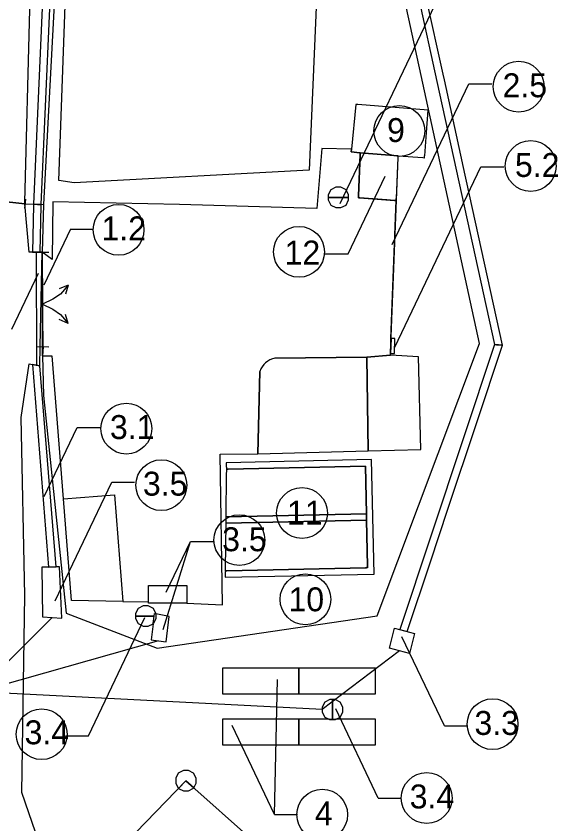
# Model space of a CAD drawing. Extents: x -438410 to -437811, y -1133174 to -1132817.
# Drawn here: x -438365.3 to -438322.9, y -1133117.4 to -1133054 of the extents above; entities that cross this region are included whole.
import ezdxf

# ---------------------------------------------------------------- set-up
doc = ezdxf.new("R2010")
doc.units = 0
for name, color, linetype in [('11 - bourané objekty', 7, 'Continuous'), ('12 - žlaby', 7, 'Continuous'), ('13 - propustky', 7, 'Continuous'), ('16 - betonové plochy', 7, 'Continuous'), ('17 - panel', 7, 'Continuous'), ('18 - asfalt', 7, 'Continuous'), ('20 - popisy', 7, 'Continuous'), ('3 - ploty a brány', 7, 'Continuous'), ('5 - obrubníky', 7, 'Continuous'), ('6 - kanalizace + šachty', 7, 'Continuous'), ('7 - elektro', 7, 'Continuous')]:
    doc.layers.add(name, color=color, linetype=linetype)

msp = doc.modelspace()

# ---------------------------------------------------------------- linework, layer by layer
at = {"layer": '11 - bourané objekty'}
for p, q in [((-438338.695, -1133060.976), (-438339.034, -1133064.474)), ((-438339.035, -1133064.486), (-438339.055, -1133064.69)), ((-438339.055, -1133064.69), (-438338.376, -1133064.756)), ((-438333.308, -1133065.146), (-438333.304, -1133065.096)), ((-438333.304, -1133065.096), (-438333.304, -1133064.996)), ((-438337.459, -1133088.816), (-438348.852, -1133089.066)), ((-438337.27, -1133097.786), (-438337.459, -1133088.816)), ((-438348.852, -1133089.066), (-438348.845, -1133089.416)), ((-438348.844, -1133089.416), (-438348.844, -1133089.465)), ((-438348.844, -1133089.465), (-438348.842, -1133089.565)), ((-438337.869, -1133093.065), (-438337.948, -1133089.331)), ((-438337.869, -1133093.065), (-438348.89, -1133093.299)), ((-438348.89, -1133093.299), (-438337.869, -1133093.065)), ((-438337.858, -1133093.565), (-438337.869, -1133093.065)), ((-438337.858, -1133093.565), (-438348.888, -1133093.8)), ((-438348.888, -1133093.8), (-438337.858, -1133093.565)), ((-438337.783, -1133097.146), (-438337.858, -1133093.565)), ((-438348.874, -1133097.576), (-438348.943, -1133097.576)), ((-438348.874, -1133097.533), (-438348.874, -1133097.576)), ((-438337.934, -1133097.296), (-438337.854, -1133097.296)), ((-438337.854, -1133097.296), (-438337.854, -1133097.256)), ((-438337.854, -1133097.256), (-438337.784, -1133097.256)), ((-438337.784, -1133097.256), (-438337.784, -1133097.146)), ((-438348.934, -1133098.035), (-438337.27, -1133097.786))]:
    msp.add_line(p, q, dxfattribs=at)
msp.add_lwpolyline([(-438360.783, -1133067.104), (-438361.974, -1133066.926), (-438360.619, -1133029.346), (-438340.823, -1133030.216), (-438342.346, -1133066.119)], close=True, dxfattribs=at)
for points in [[(-438338.642, -1133060.976), (-438338.694, -1133060.976), (-438338.695, -1133060.976)], [(-438333.019, -1133061.41), (-438338.545, -1133060.983), (-438338.642, -1133060.976)], [(-438333.297, -1133064.996), (-438333.156, -1133063.178), (-438333.019, -1133061.41)], [(-438339.034, -1133064.486), (-438339.035, -1133064.486), (-438339.035, -1133064.486)], [(-438339.034, -1133064.474), (-438339.034, -1133064.485), (-438339.034, -1133064.486)], [(-438338.376, -1133064.756), (-438338.345, -1133064.756), (-438338.344, -1133064.756)], [(-438338.344, -1133064.756), (-438338.344, -1133064.759), (-438338.344, -1133064.759)], [(-438338.344, -1133064.759), (-438335.364, -1133064.989), (-438333.454, -1133065.136), (-438333.334, -1133065.146)], [(-438333.334, -1133065.146), (-438333.308, -1133065.146), (-438333.308, -1133065.146)], [(-438333.304, -1133064.996), (-438333.297, -1133064.996)], [(-438348.845, -1133089.416), (-438348.844, -1133089.416)], [(-438348.842, -1133089.565), (-438348.694, -1133089.561), (-438337.948, -1133089.331)], [(-438337.948, -1133089.331), (-438348.694, -1133089.561), (-438348.842, -1133089.565)], [(-438337.948, -1133089.331), (-438337.869, -1133093.065), (-438337.858, -1133093.565), (-438337.783, -1133097.146), (-438337.78, -1133097.256), (-438337.78, -1133097.256), (-438337.779, -1133097.299)], [(-438348.842, -1133089.565), (-438348.844, -1133089.716), (-438348.847, -1133089.906), (-438348.89, -1133093.299)], [(-438348.89, -1133093.299), (-438348.89, -1133093.3), (-438348.896, -1133093.799)], [(-438348.896, -1133093.799), (-438348.942, -1133097.386), (-438348.944, -1133097.535)], [(-438348.888, -1133093.8), (-438348.896, -1133093.799)], [(-438348.896, -1133093.799), (-438348.888, -1133093.8)], [(-438348.944, -1133097.535), (-438348.874, -1133097.533), (-438348.794, -1133097.531), (-438337.934, -1133097.302)], [(-438348.943, -1133097.576), (-438348.941, -1133097.686), (-438348.934, -1133098.035)], [(-438337.934, -1133097.302), (-438348.794, -1133097.531), (-438348.874, -1133097.533)], [(-438337.934, -1133097.302), (-438337.934, -1133097.296)], [(-438337.779, -1133097.299), (-438337.784, -1133097.299), (-438337.854, -1133097.3), (-438337.854, -1133097.3), (-438337.934, -1133097.302)], [(-438337.784, -1133097.146), (-438337.783, -1133097.146)], [(-438337.779, -1133097.299), (-438337.779, -1133097.299)]]:
    msp.add_lwpolyline(points, dxfattribs=at)
at = {"layer": '12 - žlaby'}
for p, q in [((-438334.391, -1133049.825), (-438332.344, -1133059.164)), ((-438331.85, -1133058.606), (-438333.72, -1133050.084)), ((-438363.354, -1133068.817), (-438362.677, -1133053.437)), ((-438331.756, -1133059.035), (-438331.85, -1133058.606)), ((-438331.85, -1133058.606), (-438331.85, -1133058.606)), ((-438330.118, -1133066.503), (-438331.756, -1133059.035)), ((-438332.344, -1133059.164), (-438327.822, -1133079.8)), ((-438330.01, -1133066.994), (-438330.118, -1133066.503)), ((-438330.118, -1133066.503), (-438330.118, -1133066.503)), ((-438327.193, -1133079.837), (-438330.01, -1133066.994)), ((-438363.954, -1133068.796), (-438363.954, -1133068.796)), ((-438363.438, -1133072.554), (-438363.356, -1133068.882)), ((-438363.357, -1133068.882), (-438363.354, -1133068.817)), ((-438363.438, -1133072.554), (-438363.438, -1133072.554)), ((-438327.822, -1133079.8), (-438335.254, -1133102.137)), ((-438329.241, -1133085.984), (-438327.193, -1133079.837)), ((-438327.822, -1133079.8), (-438327.193, -1133079.837)), ((-438327.664, -1133079.809), (-438327.822, -1133079.8)), ((-438327.55, -1133079.816), (-438327.514, -1133079.816)), ((-438327.514, -1133079.816), (-438327.514, -1133079.818)), ((-438327.514, -1133079.818), (-438327.193, -1133079.837)), ((-438363.457, -1133081.454), (-438364.035, -1133081.349)), ((-438364.035, -1133081.349), (-438362.776, -1133097.231)), ((-438362.175, -1133097.219), (-438363.457, -1133081.454))]:
    msp.add_line(p, q, dxfattribs=at)
for points in [[(-438360.442, -1133026.495), (-438362.04, -1133027.991), (-438363.276, -1133053.408), (-438363.954, -1133068.796)], [(-438331.85, -1133058.606), (-438331.85, -1133058.606)], [(-438330.118, -1133066.503), (-438330.118, -1133066.503)], [(-438363.954, -1133068.796), (-438363.955, -1133068.856), (-438364.038, -1133072.559)], [(-438363.954, -1133068.796), (-438363.654, -1133068.806), (-438363.354, -1133068.817)], [(-438363.354, -1133068.817), (-438363.654, -1133068.806), (-438363.954, -1133068.796)], [(-438363.356, -1133068.882), (-438363.357, -1133068.882)], [(-438364.038, -1133072.559), (-438363.762, -1133072.557), (-438363.737, -1133072.557), (-438363.737, -1133072.557), (-438363.438, -1133072.554)], [(-438327.822, -1133079.8), (-438327.664, -1133079.809), (-438327.55, -1133079.816)], [(-438327.193, -1133079.837), (-438327.514, -1133079.818), (-438327.514, -1133079.818), (-438327.55, -1133079.816), (-438327.664, -1133079.809)], [(-438334.674, -1133102.291), (-438332.849, -1133096.813), (-438331.48, -1133092.702), (-438329.241, -1133085.984)], [(-438362.776, -1133097.231), (-438362.776, -1133097.231), (-438362.175, -1133097.219)], [(-438335.254, -1133102.137), (-438335.254, -1133102.137)], [(-438335.254, -1133102.137), (-438334.674, -1133102.291), (-438334.674, -1133102.291)]]:
    msp.add_lwpolyline(points, dxfattribs=at)
at = {"layer": '13 - propustky'}
msp.add_line((-438363.737, -1133072.502), (-438363.728, -1133081.376), dxfattribs=at)
at = {"layer": '16 - betonové plochy'}
for p, q in [((-438335.364, -1133064.989), (-438338.344, -1133064.756)), ((-438338.344, -1133064.756), (-438338.344, -1133064.906)), ((-438338.351, -1133064.905), (-438338.486, -1133068.136)), ((-438335.519, -1133068.346), (-438335.368, -1133065.118)), ((-438335.368, -1133065.116), (-438335.364, -1133065.116)), ((-438335.364, -1133065.116), (-438335.364, -1133064.989)), ((-438338.486, -1133068.136), (-438338.492, -1133068.286)), ((-438338.492, -1133068.286), (-438338.394, -1133068.286)), ((-438335.526, -1133068.496), (-438335.524, -1133068.455)), ((-438335.524, -1133068.455), (-438335.524, -1133068.346)), ((-438335.988, -1133080.621), (-438337.82, -1133080.768)), ((-438333.795, -1133080.755), (-438335.988, -1133080.621)), ((-438337.82, -1133080.768), (-438345.037, -1133080.865)), ((-438337.72, -1133088.126), (-438337.82, -1133080.768)), ((-438337.82, -1133080.768), (-438337.72, -1133088.126)), ((-438333.593, -1133088.01), (-438333.795, -1133080.755)), ((-438346.226, -1133081.897), (-438346.377, -1133088.367)), ((-438346.377, -1133088.367), (-438337.72, -1133088.126)), ((-438337.72, -1133088.126), (-438333.593, -1133088.01))]:
    msp.add_line(p, q, dxfattribs=at)
for points in [[(-438338.344, -1133064.906), (-438338.351, -1133064.905)], [(-438335.368, -1133065.118), (-438335.368, -1133065.116)], [(-438338.394, -1133068.286), (-438338.395, -1133068.293)], [(-438338.395, -1133068.293), (-438335.674, -1133068.487), (-438335.554, -1133068.496)], [(-438335.554, -1133068.496), (-438335.526, -1133068.496), (-438335.526, -1133068.496)], [(-438335.524, -1133068.346), (-438335.519, -1133068.346)]]:
    msp.add_lwpolyline(points, dxfattribs=at)
msp.add_lwpolyline([(-438361.602, -1133091.889), (-438357.615, -1133091.57), (-438356.947, -1133099.927), (-438360.987, -1133099.86)], close=True, dxfattribs=at)
msp.add_arc((-438344.71, -1133082.442), 1.611, 101.67972, 160.23687, dxfattribs=at)
at = {"layer": '17 - panel'}
for p, q in [((-438367.085, -1133068.499), (-438364.634, -1133068.771)), ((-438364.633, -1133068.772), (-438367.085, -1133068.499)), ((-438364.634, -1133068.771), (-438364.634, -1133068.626)), ((-438364.285, -1133072.562), (-438364.633, -1133068.772)), ((-438364.038, -1133072.559), (-438364.285, -1133072.562)), ((-438363.762, -1133072.557), (-438364.038, -1133072.559)), ((-438364.038, -1133072.559), (-438364.038, -1133072.56)), ((-438364.923, -1133085.522), (-438364.289, -1133081.304)), ((-438364.631, -1133099.471), (-438364.923, -1133085.522)), ((-438364.863, -1133114.9), (-438364.631, -1133099.471)), ((-438349.157, -1133105.17), (-438349.157, -1133107.17)), ((-438343.157, -1133105.17), (-438349.157, -1133105.17)), ((-438343.157, -1133107.17), (-438343.157, -1133105.17)), ((-438337.157, -1133105.17), (-438343.157, -1133105.17)), ((-438343.157, -1133105.17), (-438343.157, -1133107.17)), ((-438337.157, -1133107.17), (-438337.157, -1133105.17)), ((-438349.157, -1133107.17), (-438343.157, -1133107.17)), ((-438343.157, -1133107.17), (-438337.157, -1133107.17)), ((-438349.157, -1133109.17), (-438349.157, -1133111.17)), ((-438343.157, -1133109.17), (-438349.157, -1133109.17)), ((-438343.157, -1133111.17), (-438343.157, -1133109.17)), ((-438343.157, -1133109.17), (-438343.157, -1133111.17)), ((-438340.812, -1133109.17), (-438343.157, -1133109.17)), ((-438340.725, -1133109.214), (-438340.812, -1133109.17)), ((-438340.239, -1133109.17), (-438340.325, -1133109.214)), ((-438337.157, -1133109.17), (-438340.239, -1133109.17)), ((-438337.157, -1133111.17), (-438337.157, -1133109.17)), ((-438349.157, -1133111.17), (-438343.157, -1133111.17)), ((-438343.157, -1133111.17), (-438337.157, -1133111.17)), ((-438361.996, -1133123.207), (-438364.863, -1133114.9))]:
    msp.add_line(p, q, dxfattribs=at)
for points in [[(-438364.63, -1133068.626), (-438364.248, -1133053.526), (-438364.244, -1133053.376), (-438364.244, -1133053.371)], [(-438364.634, -1133068.626), (-438364.63, -1133068.626)], [(-438364.038, -1133072.56), (-438364.038, -1133072.559)], [(-438363.282, -1133072.553), (-438363.438, -1133072.554), (-438363.737, -1133072.557), (-438363.762, -1133072.557)], [(-438363.762, -1133072.557), (-438363.762, -1133072.557)], [(-438363.457, -1133081.454), (-438363.428, -1133079.95), (-438363.282, -1133072.553)], [(-438364.289, -1133081.304), (-438364.035, -1133081.349), (-438363.457, -1133081.454)], [(-438340.325, -1133109.214), (-438340.525, -1133109.214), (-438340.725, -1133109.214)]]:
    msp.add_lwpolyline(points, dxfattribs=at)
at = {"layer": '18 - asfalt'}
for p, q in [((-438341.362, -1133064.433), (-438341.744, -1133069.128)), ((-438339.034, -1133064.485), (-438341.362, -1133064.433)), ((-438339.055, -1133064.69), (-438339.034, -1133064.485)), ((-438338.376, -1133064.756), (-438339.055, -1133064.69)), ((-438362.435, -1133068.596), (-438362.482, -1133073.127)), ((-438352.505, -1133068.804), (-438362.435, -1133068.596)), ((-438335.939, -1133079.319), (-438335.526, -1133068.496)), ((-438335.526, -1133068.496), (-438335.554, -1133068.496)), ((-438341.744, -1133069.128), (-438352.505, -1133068.804)), ((-438363.243, -1133080.683), (-438363.282, -1133072.553)), ((-438362.482, -1133073.127), (-438363.282, -1133072.553)), ((-438363.282, -1133072.553), (-438363.263, -1133076.618)), ((-438363.263, -1133076.618), (-438363.243, -1133080.683)), ((-438335.954, -1133079.717), (-438335.943, -1133079.319)), ((-438335.943, -1133079.319), (-438335.939, -1133079.319)), ((-438337.82, -1133080.768), (-438335.988, -1133080.621)), ((-438363.243, -1133080.683), (-438362.521, -1133080.664)), ((-438362.521, -1133080.664), (-438361.624, -1133091.891)), ((-438345.037, -1133080.864), (-438337.82, -1133080.768)), ((-438346.377, -1133088.367), (-438346.226, -1133081.897)), ((-438349.335, -1133088.397), (-438346.377, -1133088.367)), ((-438349.15, -1133100.206), (-438349.335, -1133088.397)), ((-438361.624, -1133091.891), (-438361.602, -1133091.889)), ((-438361.602, -1133091.889), (-438357.615, -1133091.57)), ((-438357.615, -1133091.57), (-438356.947, -1133099.927)), ((-438354.945, -1133099.96), (-438354.945, -1133098.677)), ((-438354.945, -1133098.677), (-438351.945, -1133098.677)), ((-438351.945, -1133098.677), (-438351.945, -1133100.063)), ((-438356.947, -1133099.927), (-438354.945, -1133099.96)), ((-438351.945, -1133100.063), (-438349.15, -1133100.206))]:
    msp.add_line(p, q, dxfattribs=at)
for points in [[(-438338.492, -1133068.286), (-438338.486, -1133068.136), (-438338.351, -1133064.905), (-438338.345, -1133064.758)], [(-438338.345, -1133064.758), (-438338.345, -1133064.758), (-438338.376, -1133064.756)], [(-438338.376, -1133064.756), (-438338.376, -1133064.756)], [(-438336.259, -1133068.444), (-438338.395, -1133068.293), (-438338.492, -1133068.286)], [(-438335.554, -1133068.496), (-438335.674, -1133068.487), (-438336.259, -1133068.444)], [(-438363.263, -1133076.618), (-438363.262, -1133076.618), (-438363.263, -1133076.618)], [(-438335.988, -1133080.621), (-438335.983, -1133080.486), (-438335.954, -1133079.717)], [(-438345.037, -1133080.865), (-438345.037, -1133080.864)]]:
    msp.add_lwpolyline(points, dxfattribs=at)
msp.add_arc((-438344.71, -1133082.442), 1.611, 101.67972, 160.23687, dxfattribs=at)
at = {"layer": '20 - popisy'}
for p, q in [((-438339.93, -1133068.724), (-438331.854, -1133051.795)), ((-438335.848, -1133071.948), (-438329.841, -1133059.356)), ((-438329.841, -1133059.356), (-438328.045, -1133059.356)), ((-438335.639, -1133080.004), (-438328.889, -1133065.855)), ((-438328.889, -1133065.855), (-438327.093, -1133065.855)), ((-438339.305, -1133072.668), (-438336.405, -1133066.59)), ((-438361.051, -1133070.743), (-438363.142, -1133075.126)), ((-438361.051, -1133070.743), (-438359.255, -1133070.743)), ((-438341.102, -1133072.668), (-438339.305, -1133072.668)), ((-438363.599, -1133074.235), (-438365.689, -1133078.618)), ((-438363.114, -1133091.7), (-438360.536, -1133086.295)), ((-438360.536, -1133086.295), (-438358.739, -1133086.295)), ((-438362.257, -1133099.87), (-438357.83, -1133090.591)), ((-438357.83, -1133090.591), (-438356.033, -1133090.591)), ((-438353.79, -1133102.128), (-438351.664, -1133095.244)), ((-438353.549, -1133099.194), (-438351.664, -1133095.244)), ((-438351.664, -1133095.244), (-438349.868, -1133095.244)), ((-438359.652, -1133110.455), (-438355.225, -1133101.176)), ((-438331.758, -1133109.678), (-438335.089, -1133102.697)), ((-438345.066, -1133116.634), (-438344.845, -1133106.047)), ((-438336.943, -1133115.342), (-438340.273, -1133108.361)), ((-438345.066, -1133116.634), (-438348.396, -1133109.652)), ((-438331.758, -1133109.678), (-438329.962, -1133109.678)), ((-438361.448, -1133110.455), (-438359.652, -1133110.455)), ((-438336.943, -1133115.342), (-438335.146, -1133115.342)), ((-438345.066, -1133116.634), (-438343.269, -1133116.634))]:
    msp.add_line(p, q, dxfattribs=at)
for centre in [(-438325.935, -1133059.573), (-438335.284, -1133063.048), (-438324.988, -1133065.796), (-438357.289, -1133070.797), (-438343.144, -1133072.52), (-438356.68, -1133086.381), (-438353.94, -1133090.818), (-438342.913, -1133093.001), (-438347.82, -1133095.122), (-438342.646, -1133099.768), (-438327.976, -1133109.551), (-438363.322, -1133110.342), (-438333.143, -1133115.339), (-438341.328, -1133116.644)]:
    msp.add_circle(centre, 1.991, dxfattribs=at)
at = {"layer": '3 - ploty a brány'}
for p, q in [((-438369.536, -1133068.226), (-438364.633, -1133068.772)), ((-438364.59, -1133068.385), (-438364.67, -1133069.098)), ((-438364.633, -1133068.772), (-438363.166, -1133068.824)), ((-438363.762, -1133072.557), (-438362.761, -1133072.548)), ((-438363.211, -1133079.96), (-438363.282, -1133072.553)), ((-438361.243, -1133075.131), (-438361.943, -1133075.431)), ((-438361.243, -1133075.131), (-438361.843, -1133075.831)), ((-438361.243, -1133075.131), (-438361.443, -1133075.831)), ((-438361.843, -1133075.831), (-438362.443, -1133076.231)), ((-438362.443, -1133076.231), (-438363.243, -1133076.631)), ((-438363.243, -1133076.631), (-438362.443, -1133077.031)), ((-438362.443, -1133077.031), (-438361.843, -1133077.431)), ((-438361.843, -1133077.431), (-438361.243, -1133078.131)), ((-438361.243, -1133078.131), (-438361.443, -1133077.431)), ((-438361.243, -1133078.131), (-438361.943, -1133077.831)), ((-438363.667, -1133079.939), (-438362.755, -1133079.98))]:
    msp.add_line(p, q, dxfattribs=at)
for points in [[(-438358.834, -1133028.106), (-438361.004, -1133028.096), (-438363.166, -1133068.824), (-438363.282, -1133072.553)], [(-438363.211, -1133079.96), (-438363.243, -1133080.683), (-438363.163, -1133083.782), (-438361.404, -1133100.856), (-438354.257, -1133103.589), (-438337.029, -1133101.059), (-438329.014, -1133079.716), (-438340.141, -1133028.533), (-438354.164, -1133028.163)]]:
    msp.add_lwpolyline(points, dxfattribs=at)
at = {"layer": '5 - obrubníky'}
msp.add_line((-438335.974, -1133080.487), (-438335.368, -1133065.118), dxfattribs=at)
at = {"layer": '6 - kanalizace + šachty'}
for p, q in [((-438340.663, -1133067.654), (-438340.863, -1133068.054)), ((-438340.263, -1133067.454), (-438340.663, -1133067.654)), ((-438339.863, -1133067.454), (-438340.263, -1133067.454)), ((-438339.463, -1133067.654), (-438339.863, -1133067.454)), ((-438339.263, -1133068.054), (-438339.463, -1133067.654)), ((-438340.863, -1133068.054), (-438340.863, -1133068.254)), ((-438339.263, -1133068.254), (-438340.863, -1133068.254)), ((-438340.863, -1133068.254), (-438340.863, -1133068.454)), ((-438340.863, -1133068.254), (-438339.263, -1133068.254)), ((-438340.863, -1133068.454), (-438340.663, -1133068.854)), ((-438339.463, -1133068.854), (-438339.263, -1133068.454)), ((-438339.263, -1133068.254), (-438339.263, -1133068.054)), ((-438339.263, -1133068.454), (-438339.263, -1133068.254)), ((-438340.663, -1133068.854), (-438340.263, -1133069.054)), ((-438340.263, -1133069.054), (-438339.863, -1133069.054)), ((-438339.863, -1133069.054), (-438339.463, -1133068.854)), ((-438363.316, -1133097.243), (-438363.263, -1133101.131)), ((-438361.731, -1133101.231), (-438361.911, -1133097.214)), ((-438355.761, -1133100.472), (-438355.961, -1133100.872)), ((-438355.961, -1133100.872), (-438355.961, -1133101.072)), ((-438355.361, -1133100.272), (-438355.761, -1133100.472)), ((-438354.961, -1133100.272), (-438355.361, -1133100.272)), ((-438354.561, -1133100.472), (-438354.961, -1133100.272)), ((-438354.361, -1133100.872), (-438354.561, -1133100.472)), ((-438354.492, -1133101.072), (-438354.468, -1133100.883)), ((-438354.468, -1133100.883), (-438354.361, -1133100.905)), ((-438354.361, -1133100.905), (-438354.361, -1133100.872)), ((-438362.497, -1133101.181), (-438367.731, -1133106.418)), ((-438354.492, -1133101.072), (-438355.961, -1133101.072)), ((-438355.961, -1133101.072), (-438355.961, -1133101.272)), ((-438355.961, -1133101.072), (-438354.492, -1133101.072)), ((-438355.961, -1133101.272), (-438355.761, -1133101.672)), ((-438354.568, -1133101.671), (-438354.492, -1133101.072)), ((-438354.361, -1133101.272), (-438354.561, -1133101.672)), ((-438353.32, -1133101.123), (-438354.361, -1133100.905)), ((-438353.571, -1133103.092), (-438353.32, -1133101.123)), ((-438355.761, -1133101.672), (-438355.361, -1133101.872)), ((-438355.361, -1133101.872), (-438354.961, -1133101.872)), ((-438354.961, -1133101.872), (-438354.569, -1133101.675)), ((-438354.569, -1133101.675), (-438354.73, -1133102.945)), ((-438354.569, -1133101.675), (-438354.568, -1133101.671)), ((-438354.561, -1133101.672), (-438354.569, -1133101.675)), ((-438354.151, -1133103.018), (-438367.531, -1133106.818)), ((-438341.125, -1133107.814), (-438341.325, -1133108.214)), ((-438340.725, -1133107.614), (-438341.125, -1133107.814)), ((-438340.525, -1133107.614), (-438340.725, -1133107.614)), ((-438340.525, -1133109.17), (-438340.525, -1133107.614)), ((-438340.325, -1133107.614), (-438340.525, -1133107.614)), ((-438340.525, -1133107.614), (-438340.525, -1133109.17)), ((-438339.925, -1133107.814), (-438340.325, -1133107.614)), ((-438339.725, -1133108.214), (-438339.925, -1133107.814)), ((-438339.725, -1133108.614), (-438339.725, -1133108.214)), ((-438341.325, -1133108.614), (-438341.125, -1133109.014)), ((-438341.125, -1133109.014), (-438340.812, -1133109.17)), ((-438340.239, -1133109.17), (-438339.925, -1133109.014)), ((-438339.925, -1133109.014), (-438339.725, -1133108.614)), ((-438340.812, -1133109.17), (-438340.525, -1133109.17)), ((-438340.525, -1133109.17), (-438340.239, -1133109.17))]:
    msp.add_line(p, q, dxfattribs=at)
for points in [[(-438335.271, -1133103.802), (-438341.325, -1133108.414), (-438368.331, -1133107.018), (-438401.416, -1133090.011), (-438401.416, -1133090.011), (-438409.03, -1133084.887)], [(-438361.911, -1133097.214), (-438362.175, -1133097.219), (-438362.776, -1133097.231), (-438363.316, -1133097.243)], [(-438363.263, -1133101.131), (-438362.497, -1133101.181), (-438361.731, -1133101.231)], [(-438354.361, -1133100.905), (-438354.361, -1133101.072), (-438354.361, -1133101.272)], [(-438354.73, -1133102.945), (-438354.151, -1133103.018), (-438353.571, -1133103.092)], [(-438341.325, -1133108.214), (-438341.325, -1133108.414), (-438341.325, -1133108.614)]]:
    msp.add_lwpolyline(points, dxfattribs=at)
for points in [[(-438354.945, -1133098.677), (-438351.945, -1133098.677), (-438351.945, -1133100.077), (-438354.945, -1133100.077)], [(-438335.661, -1133102.029), (-438334.086, -1133102.448), (-438334.501, -1133104.007), (-438336.044, -1133103.596)]]:
    msp.add_lwpolyline(points, close=True, dxfattribs=at)
at = {"layer": '7 - elektro'}
for p, q in [((-438335.928, -1133079.319), (-438335.974, -1133080.487)), ((-438335.643, -1133079.327), (-438335.928, -1133079.319)), ((-438335.674, -1133080.496), (-438335.643, -1133079.327)), ((-438335.974, -1133080.487), (-438335.674, -1133080.496)), ((-438352.612, -1133113.38), (-438352.812, -1133113.78)), ((-438352.212, -1133113.18), (-438352.612, -1133113.38)), ((-438351.412, -1133113.38), (-438351.812, -1133113.18)), ((-438351.212, -1133113.78), (-438351.412, -1133113.38)), ((-438361.996, -1133124.288), (-438352.012, -1133113.98)), ((-438352.812, -1133113.78), (-438352.812, -1133114.18)), ((-438352.812, -1133114.18), (-438352.612, -1133114.58)), ((-438352.6, -1133114.586), (-438352.012, -1133113.98)), ((-438352.012, -1133113.98), (-438352.6, -1133114.586)), ((-438352.012, -1133113.98), (-438339.997, -1133124.684)), ((-438352.012, -1133113.98), (-438351.39, -1133114.534)), ((-438351.39, -1133114.534), (-438352.012, -1133113.98)), ((-438351.39, -1133114.534), (-438351.212, -1133114.18)), ((-438351.212, -1133114.18), (-438351.212, -1133113.78)), ((-438352.612, -1133114.58), (-438352.6, -1133114.586)), ((-438352.6, -1133114.586), (-438352.212, -1133114.78)), ((-438352.212, -1133114.78), (-438351.812, -1133114.78)), ((-438351.812, -1133114.78), (-438351.412, -1133114.58)), ((-438351.412, -1133114.58), (-438351.39, -1133114.534))]:
    msp.add_line(p, q, dxfattribs=at)
msp.add_lwpolyline([(-438351.812, -1133113.18), (-438352.012, -1133113.18), (-438352.212, -1133113.18)], dxfattribs=at)

# ---------------------------------------------------------------- texts
at = {"layer": '20 - popisy'}
for s, p in [('2.5', (-438327.192, -1133060.404)), ('9', (-438336.246, -1133063.916)), ('5.2', (-438326.222, -1133066.652)), ('1.2', (-438358.632, -1133071.622)), ('12', (-438344.276, -1133073.519)), ('3.1', (-438357.967, -1133087.198)), ('3.5', (-438355.38, -1133091.635)), ('11', (-438344.086, -1133093.91)), ('3.5', (-438349.169, -1133095.993)), ('10', (-438343.97, -1133100.703)), ('3.3', (-438329.396, -1133110.394)), ('3.4', (-438364.658, -1133111.127)), ('3.4', (-438334.472, -1133116.156)), ('4', (-438341.902, -1133117.488))]:
    msp.add_text(s, height=1.875, dxfattribs=at).set_placement(p)

doc.saveas('drawing.dxf')
